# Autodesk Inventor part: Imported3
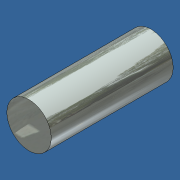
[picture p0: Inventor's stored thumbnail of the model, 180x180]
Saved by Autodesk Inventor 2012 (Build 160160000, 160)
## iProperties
Created: 2016-01
Part Number: Imported3
Material: Steel
Document SubType Name: Modeling
Designer: Admin
Density: 7.85 g/cm^3
Mass: 1.08511 g
Surface Area: 1.63363 cm^2
Volume: 0.13823 cm^3
Author: Admin
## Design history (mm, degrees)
feature "Base1"
body "Solid1"
